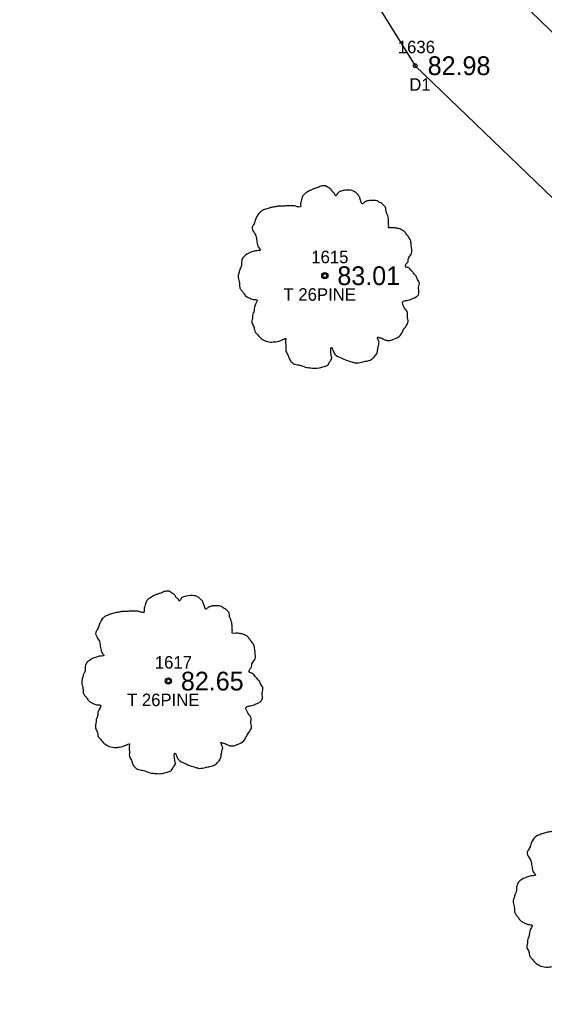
# Model space of a CAD drawing. Extents: x 2139392 to 2143384, y 505395 to 510520.
# Drawn here: x 2140947.6 to 2140989.6, y 509466 to 509543.9 of the extents above; entities that cross this region are included whole.
import ezdxf

# ---------------------------------------------------------------- set-up
doc = ezdxf.new("R2010")
doc.units = 0
for name, color, linetype in [('RD_EX_Driveway', 7, 'Continuous'), ('RD_EX_Driveway_txCode', 7, 'Continuous'), ('RD_EX_TX_Driveway_ELEV', 7, 'Continuous'), ('RD_EX_TX_VEG_ELEV', 7, 'Continuous'), ('RD_EX_VEG', 7, 'Continuous'), ('RD_EX_VEG_txCode', 7, 'Continuous'), ('RD_SMD_Locator', 7, 'Continuous')]:
    doc.layers.add(name, color=color, linetype=linetype)

msp = doc.modelspace()

# ---------------------------------------------------------------- linework, layer by layer
at = {"layer": 'RD_EX_Driveway'}
for points in [[(2140954.315, 509598.009), (2140970.973, 509570.037), (2140984.425, 509549.983), (2140986.949, 509546.035), (2140998.62, 509534.729), (2141014.131, 509524.968), (2141080.244, 509493.941)], [(2140947.592, 509589.318), (2140962.022, 509567.844), (2140979.259, 509540.16), (2140995.124, 509524.894), (2141010.756, 509515.888), (2141076.407, 509484.97)]]:
    msp.add_lwpolyline(points, dxfattribs=at)
at = {"layer": 'RD_EX_VEG'}
for centre, radius in [((2140972.031, 509523.367), 0.25), ((2140972.019, 509523.348), 0.0001), ((2140959.511, 509490.948), 0.25), ((2140959.498, 509490.929), 0.0001)]:
    msp.add_circle(centre, radius, dxfattribs=at)
for points in [[(2140972.163, 509530.534), (2140971.863, 509530.559), (2140971.538, 509530.459), (2140971.288, 509530.359), (2140971.064, 509530.284), (2140970.839, 509530.184), (2140970.539, 509530.01), (2140970.314, 509529.81), (2140970.189, 509529.56), (2140970.139, 509529.335), (2140970.089, 509529.06), (2140970.089, 509528.885), (2140969.964, 509528.86), (2140969.814, 509528.885), (2140969.564, 509528.96), (2140969.314, 509528.96), (2140969.064, 509528.96), (2140968.715, 509528.935), (2140968.365, 509528.935), (2140968.09, 509528.885), (2140967.765, 509528.835), (2140967.39, 509528.71), (2140967.04, 509528.585), (2140966.74, 509528.335), (2140966.491, 509527.86), (2140966.366, 509527.511), (2140966.216, 509527.261), (2140966.366, 509526.811), (2140966.541, 509526.461), (2140966.565, 509526.261), (2140966.64, 509525.836), (2140966.74, 509525.611), (2140966.865, 509525.411), (2140966.79, 509525.387), (2140966.416, 509525.337), (2140966.116, 509525.237), (2140965.691, 509525.012), (2140965.466, 509524.787), (2140965.366, 509524.462), (2140965.341, 509524.112), (2140965.241, 509523.912), (2140965.166, 509523.637), (2140965.141, 509523.562), (2140965.091, 509523.237), (2140965.191, 509522.788), (2140965.216, 509522.438), (2140965.341, 509522.213), (2140965.491, 509522.038), (2140965.666, 509521.788), (2140966.066, 509521.563), (2140966.391, 509521.463), (2140966.59, 509521.438), (2140966.416, 509520.938), (2140966.366, 509520.589), (2140966.241, 509520.189), (2140966.241, 509520.114), (2140966.191, 509519.639), (2140966.341, 509519.314), (2140966.416, 509518.939), (2140966.59, 509518.714), (2140966.865, 509518.415), (2140967.19, 509518.19), (2140967.69, 509518.065), (2140968.09, 509518.09), (2140968.665, 509518.265), (2140968.914, 509518.34), (2140968.889, 509518.165), (2140968.914, 509517.79), (2140968.914, 509517.365), (2140969.064, 509517.04), (2140969.164, 509516.765), (2140969.314, 509516.515), (2140969.639, 509516.291), (2140970.039, 509516.216), (2140970.464, 509516.066), (2140970.914, 509515.991), (2140971.413, 509515.966), (2140972.013, 509516.116), (2140972.288, 509516.241), (2140972.388, 509516.415), (2140972.588, 509516.79), (2140972.538, 509517.015), (2140972.563, 509517.615), (2140972.663, 509517.44), (2140972.838, 509517.09), (2140973.338, 509516.79), (2140973.737, 509516.615), (2140974.212, 509516.465), (2140974.512, 509516.39), (2140974.987, 509516.465), (2140975.362, 509516.54), (2140975.736, 509516.665), (2140976.036, 509516.94), (2140976.211, 509517.215), (2140976.261, 509517.49), (2140976.336, 509517.865), (2140976.386, 509518.04)], [(2140976.386, 509518.04), (2140976.311, 509518.215), (2140976.261, 509518.465), (2140976.336, 509518.44), (2140976.511, 509518.39), (2140976.786, 509518.265), (2140977.011, 509518.19), (2140977.336, 509518.215), (2140977.611, 509518.315), (2140978.06, 509518.59), (2140978.335, 509519.064), (2140978.61, 509519.464), (2140978.685, 509519.789), (2140978.635, 509520.014), (2140978.61, 509520.514), (2140978.41, 509520.764), (2140978.36, 509520.888), (2140978.26, 509521.288), (2140978.335, 509521.338), (2140978.61, 509521.388), (2140978.985, 509521.513), (2140979.26, 509521.638), (2140979.485, 509521.813), (2140979.56, 509522.038), (2140979.535, 509522.438), (2140979.585, 509522.838), (2140979.51, 509522.988), (2140979.41, 509523.137), (2140979.335, 509523.337), (2140979.185, 509523.487), (2140979.085, 509523.637), (2140978.985, 509523.737), (2140978.86, 509523.887), (2140978.685, 509524.012), (2140978.535, 509524.062), (2140978.485, 509524.212), (2140978.635, 509524.412), (2140978.685, 509524.512), (2140978.71, 509524.737), (2140978.935, 509525.087), (2140978.985, 509525.486), (2140978.935, 509525.911), (2140978.885, 509526.186), (2140978.735, 509526.461), (2140978.535, 509526.711), (2140978.41, 509526.886), (2140978.235, 509527.011), (2140977.911, 509527.136), (2140977.661, 509527.186), (2140977.311, 509527.186), (2140977.111, 509527.236), (2140977.136, 509527.286), (2140977.136, 509527.436), (2140977.136, 509527.711), (2140977.061, 509528.16), (2140976.911, 509528.66), (2140976.911, 509528.685), (2140976.811, 509528.935), (2140976.586, 509529.135), (2140976.411, 509529.235), (2140976.211, 509529.36), (2140975.961, 509529.385), (2140975.662, 509529.385), (2140975.387, 509529.335), (2140975.187, 509529.235), (2140975.012, 509529.11), (2140974.937, 509529.26), (2140974.837, 509529.56), (2140974.787, 509529.71), (2140974.637, 509529.885), (2140974.412, 509530.084), (2140973.962, 509530.209), (2140973.338, 509530.134), (2140973.038, 509529.935), (2140972.888, 509529.76), (2140972.838, 509529.885), (2140972.638, 509530.084), (2140972.538, 509530.259), (2140972.363, 509530.384), (2140972.213, 509530.484), (2140972.113, 509530.534)], [(2140959.643, 509498.116), (2140959.343, 509498.141), (2140959.018, 509498.041), (2140958.768, 509497.941), (2140958.543, 509497.866), (2140958.318, 509497.766), (2140958.018, 509497.591), (2140957.794, 509497.391), (2140957.669, 509497.141), (2140957.619, 509496.916), (2140957.569, 509496.641), (2140957.569, 509496.466), (2140957.444, 509496.441), (2140957.294, 509496.466), (2140957.044, 509496.541), (2140956.794, 509496.541), (2140956.544, 509496.541), (2140956.194, 509496.516), (2140955.844, 509496.516), (2140955.57, 509496.466), (2140955.245, 509496.416), (2140954.87, 509496.291), (2140954.52, 509496.166), (2140954.22, 509495.916), (2140953.97, 509495.442), (2140953.845, 509495.092), (2140953.695, 509494.842), (2140953.845, 509494.392), (2140954.02, 509494.042), (2140954.045, 509493.842), (2140954.12, 509493.418), (2140954.22, 509493.193), (2140954.345, 509492.993), (2140954.27, 509492.968), (2140953.895, 509492.918), (2140953.595, 509492.818), (2140953.171, 509492.593), (2140952.946, 509492.368), (2140952.846, 509492.043), (2140952.821, 509491.693), (2140952.721, 509491.493), (2140952.646, 509491.219), (2140952.621, 509491.144), (2140952.571, 509490.819), (2140952.671, 509490.369), (2140952.696, 509490.019), (2140952.821, 509489.794), (2140952.971, 509489.619), (2140953.146, 509489.369), (2140953.545, 509489.144), (2140953.87, 509489.044), (2140954.07, 509489.02), (2140953.895, 509488.52), (2140953.845, 509488.17), (2140953.72, 509487.77), (2140953.72, 509487.695), (2140953.67, 509487.22), (2140953.82, 509486.895), (2140953.895, 509486.521), (2140954.07, 509486.296), (2140954.345, 509485.996), (2140954.67, 509485.771), (2140955.17, 509485.646), (2140955.57, 509485.671), (2140956.144, 509485.846), (2140956.394, 509485.921), (2140956.369, 509485.746), (2140956.394, 509485.371), (2140956.394, 509484.946), (2140956.544, 509484.621), (2140956.644, 509484.347), (2140956.794, 509484.097), (2140957.119, 509483.872), (2140957.519, 509483.797), (2140957.943, 509483.647), (2140958.393, 509483.572), (2140958.893, 509483.547), (2140959.493, 509483.697), (2140959.768, 509483.822), (2140959.868, 509483.997), (2140960.068, 509484.372), (2140960.018, 509484.596), (2140960.043, 509485.196), (2140960.142, 509485.021), (2140960.317, 509484.671), (2140960.817, 509484.372), (2140961.217, 509484.197), (2140961.692, 509484.047), (2140961.992, 509483.972), (2140962.466, 509484.047), (2140962.841, 509484.122), (2140963.216, 509484.247), (2140963.516, 509484.521), (2140963.691, 509484.796), (2140963.741, 509485.071), (2140963.816, 509485.446), (2140963.866, 509485.621)], [(2140963.866, 509485.621), (2140963.791, 509485.796), (2140963.741, 509486.046), (2140963.816, 509486.021), (2140963.991, 509485.971), (2140964.266, 509485.846), (2140964.491, 509485.771), (2140964.815, 509485.796), (2140965.09, 509485.896), (2140965.54, 509486.171), (2140965.815, 509486.646), (2140966.09, 509487.045), (2140966.165, 509487.37), (2140966.115, 509487.595), (2140966.09, 509488.095), (2140965.89, 509488.345), (2140965.84, 509488.47), (2140965.74, 509488.87), (2140965.815, 509488.92), (2140966.09, 509488.97), (2140966.465, 509489.094), (2140966.74, 509489.219), (2140966.965, 509489.394), (2140967.039, 509489.619), (2140967.015, 509490.019), (2140967.064, 509490.419), (2140966.99, 509490.569), (2140966.89, 509490.719), (2140966.815, 509490.919), (2140966.665, 509491.069), (2140966.565, 509491.219), (2140966.465, 509491.318), (2140966.34, 509491.468), (2140966.165, 509491.593), (2140966.015, 509491.643), (2140965.965, 509491.793), (2140966.115, 509491.993), (2140966.165, 509492.093), (2140966.19, 509492.318), (2140966.415, 509492.668), (2140966.465, 509493.068), (2140966.415, 509493.493), (2140966.365, 509493.767), (2140966.215, 509494.042), (2140966.015, 509494.292), (2140965.89, 509494.467), (2140965.715, 509494.592), (2140965.39, 509494.717), (2140965.14, 509494.767), (2140964.79, 509494.767), (2140964.591, 509494.817), (2140964.616, 509494.867), (2140964.616, 509495.017), (2140964.616, 509495.292), (2140964.541, 509495.742), (2140964.391, 509496.241), (2140964.391, 509496.266), (2140964.291, 509496.516), (2140964.066, 509496.716), (2140963.891, 509496.816), (2140963.691, 509496.941), (2140963.441, 509496.966), (2140963.141, 509496.966), (2140962.866, 509496.916), (2140962.666, 509496.816), (2140962.491, 509496.691), (2140962.416, 509496.841), (2140962.317, 509497.141), (2140962.267, 509497.291), (2140962.117, 509497.466), (2140961.892, 509497.666), (2140961.442, 509497.791), (2140960.817, 509497.716), (2140960.517, 509497.516), (2140960.367, 509497.341), (2140960.317, 509497.466), (2140960.117, 509497.666), (2140960.018, 509497.841), (2140959.843, 509497.966), (2140959.693, 509498.066), (2140959.593, 509498.116)], [(2140994.174, 509480.548), (2140993.875, 509480.573), (2140993.55, 509480.473), (2140993.3, 509480.373), (2140993.075, 509480.298), (2140992.85, 509480.198), (2140992.55, 509480.023), (2140992.325, 509479.823), (2140992.2, 509479.574), (2140992.15, 509479.349), (2140992.1, 509479.074), (2140992.1, 509478.899), (2140991.975, 509478.874), (2140991.825, 509478.899), (2140991.576, 509478.974), (2140991.326, 509478.974), (2140991.076, 509478.974), (2140990.726, 509478.949), (2140990.376, 509478.949), (2140990.101, 509478.899), (2140989.776, 509478.849), (2140989.402, 509478.724), (2140989.052, 509478.599), (2140988.752, 509478.349), (2140988.502, 509477.874), (2140988.377, 509477.524), (2140988.227, 509477.275), (2140988.377, 509476.825), (2140988.552, 509476.475), (2140988.577, 509476.275), (2140988.652, 509475.85), (2140988.752, 509475.625), (2140988.877, 509475.425), (2140988.802, 509475.4), (2140988.427, 509475.35), (2140988.127, 509475.25), (2140987.702, 509475.026), (2140987.477, 509474.801), (2140987.377, 509474.476), (2140987.352, 509474.126), (2140987.253, 509473.926), (2140987.178, 509473.651), (2140987.153, 509473.576), (2140987.103, 509473.251), (2140987.203, 509472.801), (2140987.228, 509472.452), (2140987.352, 509472.227), (2140987.502, 509472.052), (2140987.677, 509471.802), (2140988.077, 509471.577), (2140988.402, 509471.477), (2140988.602, 509471.452), (2140988.427, 509470.952), (2140988.377, 509470.602), (2140988.252, 509470.203), (2140988.252, 509470.128), (2140988.202, 509469.653), (2140988.352, 509469.328), (2140988.427, 509468.953), (2140988.602, 509468.728), (2140988.877, 509468.428), (2140989.202, 509468.204), (2140989.701, 509468.079), (2140990.101, 509468.104), (2140990.676, 509468.278), (2140990.926, 509468.353), (2140990.901, 509468.179), (2140990.926, 509467.804), (2140990.926, 509467.379), (2140991.076, 509467.054), (2140991.176, 509466.779), (2140991.326, 509466.529), (2140991.651, 509466.304), (2140992.05, 509466.229), (2140992.475, 509466.079), (2140992.925, 509466.004), (2140993.425, 509465.979), (2140994.025, 509466.129), (2140994.299, 509466.254), (2140994.399, 509466.429), (2140994.599, 509466.804), (2140994.549, 509467.029), (2140994.574, 509467.629), (2140994.674, 509467.454), (2140994.849, 509467.104), (2140995.349, 509466.804), (2140995.749, 509466.629), (2140996.224, 509466.479), (2140996.523, 509466.404), (2140996.998, 509466.479), (2140997.373, 509466.554), (2140997.748, 509466.679), (2140998.048, 509466.954), (2140998.223, 509467.229), (2140998.273, 509467.504), (2140998.348, 509467.879), (2140998.398, 509468.054)]]:
    msp.add_spline(points, degree=3, dxfattribs=at)
at = {"layer": 'RD_SMD_Locator'}
for centre in [(2140979.259, 509540.16), (2140972.031, 509523.367), (2140959.511, 509490.948)]:
    msp.add_circle(centre, 0.15, dxfattribs=at)

# ---------------------------------------------------------------- texts
at = {"layer": 'RD_EX_Driveway_txCode'}
for s, p in [('1636', (2140977.865, 509541.16)), ('D1', (2140978.786, 509538.16))]:
    msp.add_text(s, height=1, dxfattribs=at).set_placement(p)
at = {"layer": 'RD_EX_TX_Driveway_ELEV'}
msp.add_text('82.98', height=1.5, dxfattribs=at).set_placement((2140980.259, 509539.41))
at = {"layer": 'RD_EX_TX_VEG_ELEV'}
for s, p in [('83.01', (2140973.031, 509522.617)), ('82.65', (2140960.511, 509490.198))]:
    msp.add_text(s, height=1.5, dxfattribs=at).set_placement(p)
at = {"layer": 'RD_EX_VEG_txCode'}
for s, p in [('1615', (2140970.944, 509524.367)), ('T 26PINE', (2140968.72, 509521.367)), ('1617', (2140958.424, 509491.948)), ('T 26PINE', (2140956.2, 509488.948))]:
    msp.add_text(s, height=1, dxfattribs=at).set_placement(p)

doc.saveas('drawing.dxf')
